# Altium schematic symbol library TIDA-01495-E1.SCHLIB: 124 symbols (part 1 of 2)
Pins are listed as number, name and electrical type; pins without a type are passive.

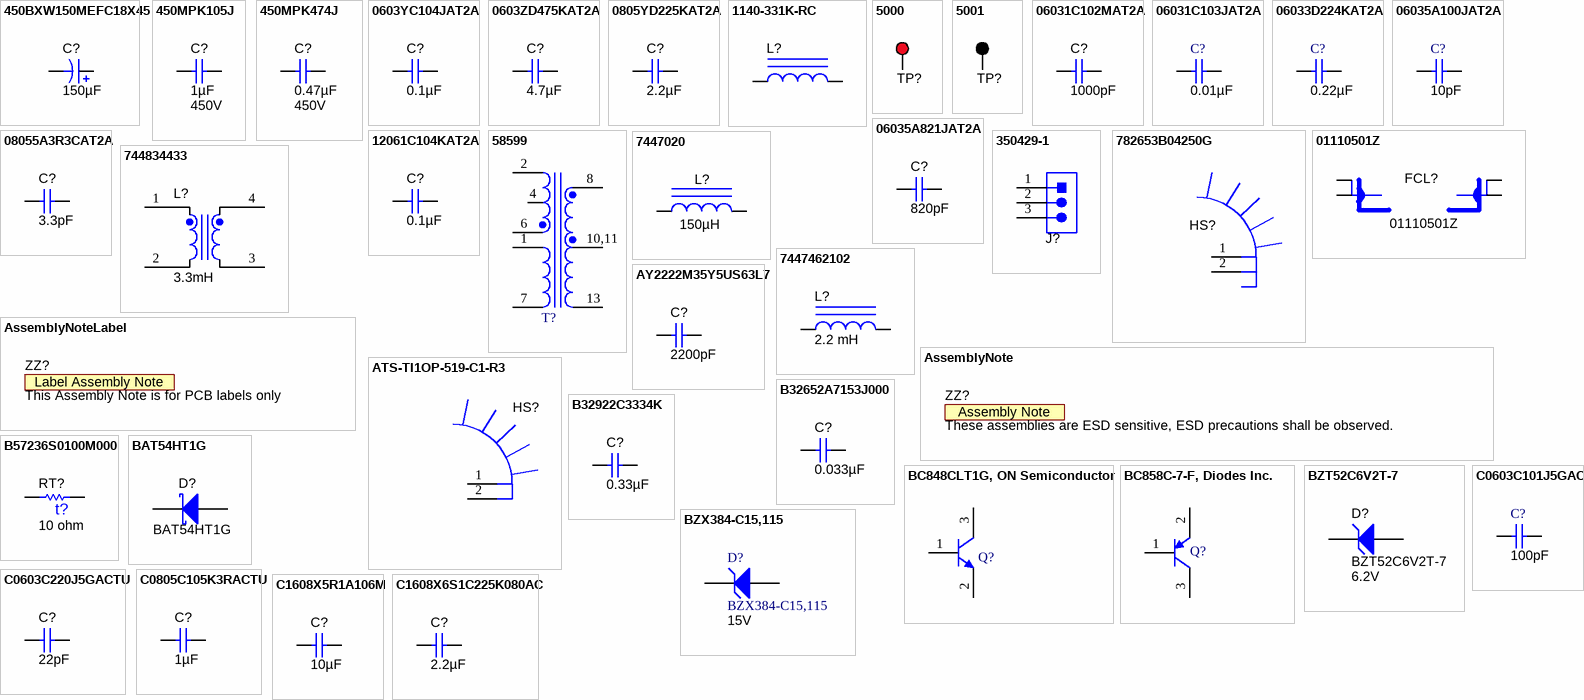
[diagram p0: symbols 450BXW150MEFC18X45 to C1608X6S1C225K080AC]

## 450BXW150MEFC18X45
designator C?  ValueDisplayed: 150µF  (hidden comment: 450BXW150MEFC18X45)
CAP, AL, 150 µF, 450 V, +/- 20%, TH; Manufacturer: Rubycon; Polarized: Y; CompType: Capacitor; Value: 150uF; U/M: EA; Cap_F: 0.00015; Tolerance_%: 20; VDC_V: 450; Value2: 450V; IRMS_A: 1; TaMin_C: -40; TaMax_C: 105; Cap_Case: 18x45mm; SizeAreaWB_mm2: 400; SizeArea_mm2: 324; SizeX_mm: 18; SizeZ_mm: 47; AEC Category: Q200; AEC Qualified: N; Green_Lifecycle: Not Set; Green_REACh: Incomplete
signal-integrity model Cap
simulation model Cap
footprint BXW_1800x4500
footprint KXG_1800x4000_horizontalDown (TH, 2-Leads, Dia 18mm, Pin Spacing 7.5mm)
pins: 1 +, 2 -

## 450MPK105J
designator C?  ValueDisplayed: 1µF  Value2: 450V  (hidden comment: 450MPK105J)
CAP, Film, 1 µF, 450 V, +/- 5%, TH; Manufacturer: Rubycon; Polarized: N; CompType: Capacitor; Value: 1uF; U/M: EA; Cap_F: 0.000001; Tolerance_%: 5; Value1: Unknown; VDC_V: 450; TaMin_C: -40; TaMax_C: 105; Cap_Case: 18x9.5mm
signal-integrity model Cap
simulation model Cap
footprint MPK_1800x950
pins: 1, 2

## 450MPK474J
designator C?  ValueDisplayed: 0.47µF  Value2: 450V  (hidden comment: 450MPK474J)
CAP, Film, 0.47 µF, 450 V, +/- 5%, TH; Manufacturer: Rubycon; Polarized: N; CompType: Capacitor; Value: 0.47uF; U/M: EA; Cap_F: 0.00000047; Tolerance_%: 5; Value1: Unknown; VDC_V: 450; TaMin_C: -40; TaMax_C: 105; Cap_Case: 18x6.5mm; AEC Category: Q200
signal-integrity model Cap
simulation model Cap
footprint MPK_1800x650
pins: 1, 2

## 0603YC104JAT2A
designator C?  ValueDisplayed: 0.1µF  (hidden comment: 0603YC104JAT2A)
CAP, CERM, 0.1 µF, 16 V, +/- 5%, X7R, 0603; Manufacturer: AVX; Polarized: N; CompType: Capacitor; Value: 0.1uF; U/M: EA; Cap_F: 0.0000001; Tolerance_%: 5; ESR_ohm: 0.039; Value1: 0.039 ohm; VDC_V: 16; Value2: 16V; TaMin_C: -55; TaMax_C: 125; Cap_Case: 0603
signal-integrity model Cap
simulation model Cap
footprint 0603
footprint 0603M
footprint 0603L
footprint 0603_HV
footprint 0603S
pins: 1, 2

## 0603ZD475KAT2A
designator C?  ValueDisplayed: 4.7µF  (hidden comment: 0603ZD475KAT2A)
CAP, CERM, 4.7 µF, 10 V, +/- 10%, X5R, 0603; Manufacturer: AVX; Polarized: N; CompType: Capacitor; Value: 4.7uF; U/M: EA; Cap_F: 0.0000047; Tolerance_%: 10; Value1: Unknown; Value2: 10V; TaMin_C: -55; TaMax_C: 85; Cap_Case: 0603; SizeArea_mm2: 1.28; SizeAreaWB_mm2: 4.68; SizeX_mm: 1.6; SizeY_mm: 0.8; SizeZ_mm: 1; AEC Category: Q200; Green_Lifecycle: Active; Green_REACh: Passed
signal-integrity model Cap
simulation model Cap
footprint 0603
footprint 0603M
footprint 0603L
footprint 0603_HV
footprint 0603S
pins: 1, 2

## 0805YD225KAT2A
designator C?  ValueDisplayed: 2.2µF  (hidden comment: 0805YD225KAT2A)
CAP, CERM, 2.2 µF, 16 V, +/- 10%, X5R, 0805; Manufacturer: AVX; Polarized: N; CompType: Capacitor; Value: 2.2uF; U/M: EA; Cap_F: 0.0000022; Tolerance_%: 10; ESR_ohm: 0.009; Value1: 0.009 ohm; VDC_V: 16; Value2: 16V; TaMin_C: -55; TaMax_C: 85; Cap_Case: 0805
signal-integrity model Cap
simulation model Cap
footprint 0805_HV
footprint 0805
footprint 0805M
footprint 0805L
pins: 1, 2

## 1140-331K-RC
designator L?
Inductor, Ferrite, 330 µH, 6.1 A, 0.074 ohm, TH; DCR_ohm: 0.074; AEC Category: Q200
signal-integrity model Inductor
simulation model Inductor
footprint IND_CUST
pins: 1, 2

## 5000
designator TP?  (value not drawn)
Test Point, Miniature, Red, TH; Manufacturer: Keystone; CompType: Test Point Loop; U/M: EA
footprint Keystone5000
pins: 1

## 5001
designator TP?  (value not drawn)
Test Point, Miniature, Black, TH; Manufacturer: Keystone; CompType: Test Point Loop; U/M: EA
footprint Keystone5001
pins: 1

## 06031C102MAT2A
designator C?  ValueDisplayed: 1000pF  (hidden comment: 06031C102MAT2A)
CAP, CERM, 1000 pF, 100 V, +/- 20%, X7R, 0603; Manufacturer: AVX; Polarized: N; CompType: Capacitor; Value: 1000pF; U/M: EA; Cap_F: 0.000000001; Tolerance_%: 20; ESR_ohm: 0.276; Value1: 0.276 ohm; VDC_V: 100; Value2: 100V; TaMin_C: -55; TaMax_C: 125; Cap_Case: 0603
signal-integrity model Cap
simulation model Cap
footprint 0603
footprint 0603M
footprint 0603L
footprint 0603_HV
footprint 0603S
pins: 1, 2

## 06031C103JAT2A
designator C?  ValueDisplayed: 0.01µF  (hidden comment: 06031C103JAT2A)
CAP, CERM, 0.01 µF, 100 V, +/- 5%, X7R, 0603; Manufacturer: AVX; Polarized: N; CompType: Capacitor; Value: 0.01uF; U/M: EA; Cap_F: 0.00000001; Tolerance_%: 5; ESR_ohm: 0.098; Value1: 0.098 ohm; VDC_V: 100; Value2: 100V; TaMin_C: -55; TaMax_C: 125; Cap_Case: 0603
signal-integrity model Cap
simulation model Cap
footprint 0603
footprint 0603M
footprint 0603L
footprint 0603_HV
footprint 0603S
pins: 1, 2

## 06033D224KAT2A
designator C?  ValueDisplayed: 0.22µF  (hidden comment: 06033D224KAT2A)
CAP, CERM, 0.22 µF, 25 V, +/- 10%, X5R, 0603; Manufacturer: AVX; Polarized: N; CompType: Capacitor; Value: 0.22uF; U/M: EA; Cap_F: 0.00000022; Tolerance_%: 10; ESR_ohm: 0.036; Value1: 0.036 ohm; VDC_V: 25; Value2: 25V; TaMin_C: -55; TaMax_C: 85; Cap_Case: 0603
signal-integrity model Cap
simulation model Cap
footprint 0603
footprint 0603M
footprint 0603L
footprint 0603_HV
footprint 0603S
pins: 1, 2

## 06035A100JAT2A
designator C?  ValueDisplayed: 10pF  (hidden comment: 06035A100JAT2A)
CAP, CERM, 10 pF, 50 V, +/- 5%, C0G/NP0, 0603; Manufacturer: AVX; Polarized: N; CompType: Capacitor; Value: 10pF; U/M: EA; Cap_F: 0.00000000001; Tolerance_%: 5; ESR_ohm: 0.403; Value1: 0.403 ohm; VDC_V: 50; Value2: 50V; TaMin_C: -55; TaMax_C: 125; Cap_Case: 0603
signal-integrity model Cap
simulation model Cap
footprint 0603
footprint 0603M
footprint 0603L
footprint 0603_HV
footprint 0603S
pins: 1, 2

## 06035A821JAT2A
designator C?  ValueDisplayed: 820pF  (hidden comment: 06035A821JAT2A)
CAP, CERM, 820 pF, 50 V, +/- 5%, C0G/NP0, 0603; Manufacturer: AVX; Polarized: N; CompType: Capacitor; Value: 820pF; U/M: EA; Cap_F: 0.00000000082; Tolerance_%: 5; ESR_ohm: 0.052; Value1: 0.052 ohm; VDC_V: 50; Value2: 50V; TaMin_C: -55; TaMax_C: 125; Cap_Case: 0603
signal-integrity model Cap
simulation model Cap
footprint 0603
footprint 0603M
footprint 0603L
footprint 0603_HV
footprint 0603S
pins: 1, 2

## 08055A3R3CAT2A
designator C?  ValueDisplayed: 3.3pF  (hidden comment: 08055A3R3CAT2A)
CAP, CERM, 3.3 pF, 50 V, +/- 8%, C0G/NP0, 0805; Manufacturer: AVX; Polarized: N; CompType: Capacitor; Value: 3.3pF; U/M: EA; Cap_F: 0.0000000000033; Tolerance_%: 8; ESR_ohm: 3.467; Value1: 3.467 ohm; VDC_V: 50; Value2: 50V; TaMin_C: -55; TaMax_C: 125; Cap_Case: 0805; SizeArea_mm2: 2.5; SizeAreaWB_mm2: 6.75; SizeX_mm: 2; SizeY_mm: 1.25; SizeZ_mm: 1.45; AEC Category: Q200; Green_Lifecycle: Not Set; Green_REACh: Incomplete
signal-integrity model Cap
simulation model Cap
footprint 0805_HV
footprint 0805_HV1
footprint 0805
footprint 0805M
footprint 0805L
pins: 1, 2

## 12061C104KAT2A
designator C?  ValueDisplayed: 0.1µF  (hidden comment: 12061C104KAT2A)
CAP, CERM, 0.1 µF, 100 V, +/- 10%, X7R, 1206; Manufacturer: AVX; Polarized: N; CompType: Capacitor; Value: 0.1uF; U/M: EA; Cap_F: 0.0000001; Tolerance_%: 10; ESR_ohm: 0.037; Value1: 0.037 ohm; VDC_V: 100; Value2: 100V; TaMin_C: -55; TaMax_C: 125; Cap_Case: 1206; SizeArea_mm2: 5.12; SizeAreaWB_mm2: 10.92; SizeX_mm: 3.2; SizeY_mm: 1.6; SizeZ_mm: 1.35; AEC Category: Q200; Green_Lifecycle: Active; Green_REACh: Passed
signal-integrity model Cap
simulation model Cap
footprint 1206
footprint 1206M
footprint 1206L
pins: 1, 2

## 58599
designator T?  (value not drawn)
Transformer, TH; Manufacturer: Payton; SymbolCreator: Altium; U/M: EA
footprint Payton_58599
footprint PCBComponent_1 - duplicate
footprint WE_750343661_CUS (TRANSFORMER, TH, 14-PIN)
pins: 1, 2, 4, 6, 7, 8, 10,11, 11, 13

## 350429-1
designator J?  (value not drawn)
Header(Shrouded), 6.35mm, 3x1, Tin, TH; Manufacturer: TE Connectivity; SymbolCreator: a0799628; U/M: EA
footprint TE_350429-1
pins: 1, 2, 3
3 alternate drawings of the same symbol

## 782653B04250G
designator HS?  (value not drawn)
HEATSINK VERT MAX CLIP, BLACK, 4.25 INCHES; Manufacturer: Aavid; SymbolCreator: a0411947
footprint HEATSINK_782653B04250G (Aavid)
pins: 1, 2

## 01110501Z
designator FCL?
FUSE CLIP, CARTRIDGE, 250V, 10A, PCB; Manufacturer: LITTELFUSE; SymbolCreator: x0199378
footprint LITTELFUSE_01110501Z (FUSE CLIP, CARTRIDGE, 250V, 10A, PCB)
pins: 1, 2, 3, 4

## 7447020
designator L?, comment ValueDisplayed: 150µH  (hidden comment: 7447076)
Inductor, Toroid, Powdered Iron, 150 µH, 5A, TH; Manufacturer: Wurth Elektronik; Value: 150uH; Value1: 0.16 ohm
signal-integrity model Inductor
simulation model Inductor
footprint IND_7447020
pins: 1, 2

## 744834433
designator L?  ValueDisplayed: 3.3mH  (hidden comment: 744834433)
Coupled inductor, 3.3 mH, 5 A, 0.037 ohm, TH; Manufacturer: Wurth Elektronik; SymbolCreator: a0412235; Value: 3.3mH; Ind_H: 3.3E-3; DCR_ohm: 0.037; AEC Category: Q200
footprint WE-CMBH
pins: 1, 2, 3, 4
1 alternate drawing of the same symbol

## 7447462102
designator L?, comment ValueDisplayed: 2.2 mH  (hidden comment: 744741222)
FIXED IND 2.2MH 210MA 11 OHM TH; Manufacturer: Wurth Elektronik; CompType: Inductor; Value: 1mH; Ind_H: 1.0E-3; Irms: 0.25A @ 40C rise; Isat: 0.27A @ 10% inductance drop; DCR_ohm: 4.38; Value1: 4.38 ohm; Value2: 0.25A; Material: Ferrite; SizeAreaWB_mm2: 64; SizeArea_mm2: 36; SizeX_mm: 6; SizeZ_mm: 8.5; AEC Category: Q200; Green_Lifecycle: Active; Green_REACh: Passed
signal-integrity model Inductor
simulation model Inductor
footprint WE-TI_5075
pins: 1, 2

## AssemblyNote
designator ZZ?, comment These assemblies are ESD sensitive, ESD precautions shall be observed.  (no BOM)
SymbolCreator: codlsc; CompType: AssemblyNote
footprint AssemblyNote

## AssemblyNoteLabel
designator ZZ?, comment This Assembly Note is for PCB labels only  (no BOM)
SymbolCreator: a0412235
footprint AssemblyNoteLabel

## ATS-TI1OP-519-C1-R3
designator HS?
Heat Sink, Vertical; Manufacturer: Advanced Thermal Solutions; SymbolCreator: a0799628; Green_Lifecycle: Not Set; Green_REACh: Incomplete
footprint HEATSINK_782653B04250G - duplicate (Aavid)
footprint HEATSINK_782653B04250G - duplicate1 (Aavid)
pins: 1, 2

## AY2222M35Y5US63L7
designator C?  ValueDisplayed: 2200pF  (hidden comment: AY2222M35Y5US63L7)
CAP, CERM, 2200 pF, 300 V, +/- 20%, Y5U, AEC-Q200 Grade 1, D9.5xT5mm; Manufacturer: Vishay-Bccomponents; Polarized: N; CompType: Capacitor; Value: 2200pF; U/M: EA; Cap_F: 0.0000000022; Tolerance_%: 20; Value1: Unknown; VDC_V: 300; Value2: 300V; TaMin_C: -55; TaMax_C: 125; Cap_Case: 9.5x5mm; SizeArea_mm2: 47.5; SizeAreaWB_mm2: 80.5; SizeX_mm: 9.5; SizeY_mm: 5; SizeZ_mm: 14.5; AEC Category: Q200; AEC Qualified: Y; AEC Grade: 1
signal-integrity model Cap
simulation model Cap
footprint CD45_700x600x1100 (TH, 2-Leads, Dia 7mm, Pin Spacing 10 mm)
pins: 1, 2

## B32652A7153J000
designator C?, comment ValueDisplayed: 0.033µF  (hidden comment: B32642B0333J)
CAP FILM 0.033UF 5% 1KVDC RADIAL; Manufacturer: TDK; Polarized: N; CompType: Capacitor; U/M: EA; Cap_F: 0.000000033; Tolerance_%: 5; VDC_V: 1250; Value2: 1250V; TaMin_C: -55; TaMax_C: 100; Cap_Case: 18x7x12.5; SizeAreaWB_mm2: 180; SizeArea_mm2: 126; SizeX_mm: 18; SizeY_mm: 7; SizeZ_mm: 12.5; AEC Category: Q200; AEC Qualified: Y; AEC Grade: 3; Green_Lifecycle: Not Set; Green_REACh: Incomplete; VAC: 500
signal-integrity model Cap
simulation model Cap
footprint B32652_1800x700x1250
pins: 1, 2

## B32922C3334K
designator C?  ValueDisplayed: 0.33µF  (hidden comment: B32922C3334K)
CAP, Film, 0.33 µF, X2 305 VAC, +/- 10%, TH; Manufacturer: TDK; Polarized: N; CompType: Capacitor; Value: 0.33uF; U/M: EA; Cap_F: 0.00000033; Tolerance_%: 10; TaMin_C: -40; TaMax_C: 110; Cap_Case: 18x8x14.5mm; SizeAreaWB_mm2: 210; SizeArea_mm2: 153; SizeX_mm: 18; SizeY_mm: 8.5; SizeZ_mm: 14.5; AEC Category: Q200; VAC_X: 305
signal-integrity model Cap
simulation model Cap
footprint B32922_14.5mm
pins: 1, 2

## B57236S0100M000
designator RT?  value 10 ohm  (hidden comment: B57236S0100M000)
Thermistor NTC, 10 ohm, 20%, Disc_11.5mmx6mm; Manufacturer: EPCOS Inc; Tolerance_%: 20; Power_W: 2.1; TaMin_C: -55; TaMax_C: 170; U/M: EA
footprint THERM_B57236S0
pins: 1, 2

## BAT54HT1G
designator D?
Diode, Schottky, 30V, 0.2A, SOD-323; Manufacturer: ON Semiconductor; Value: 0.35V; U/M: EA; Vf_V: 0.35; Io_A: 0.2; Vr_V: 30
signal-integrity model Diode
footprint sod-323
pins: 1 K, 2 A

## BC848CLT1G, ON Semiconductor
designator Q?, comment BC848CLT1G  (value not drawn)
Transistor, NPN, 30 V, 0.1 A, SOT-23; Manufacturer: ON Semiconductor; CompType: BJT; PNP: 0; NPN: 1; Vceo_V: 30; Vcesat1_V: 0.7; Value: 30 V; IcRated_A: 0.1; Value1: 0.1 A; HfeMax: 800; TaMin_C: -55; TaMax_C: 150; U/M: EA
footprint SOT-23
footprint SOT-23M
footprint SOT-23L
pins: 1 B, 2 E, 3 C

## BC858C-7-F, Diodes Inc.
designator Q?, comment BC858C-7-F  (value not drawn)
Transistor, PNP, 30 V, 0.1 A, SOT-23; Manufacturer: Diodes Inc.; CompType: BJT; PNP: 1; NPN: 0; Vceo_V: 30; Vcesat1_V: 0.075; Value: 30 V; IcRated_A: 0.1; Value1: 0.1 A; HfeMax: 600; TaMin_C: -65; TaMax_C: 150; U/M: EA
footprint SOT-23
footprint SOT-23M
footprint SOT-23L
simulation model DI_BC858C
pins: 1 B, 2 E, 3 C

## BZT52C6V2T-7
designator D?  value 6.2V
Diode, Zener, 6.2 V, 300 mW, SOD-523; Manufacturer: Diodes Inc.; SymbolCreator: a0412235; U/M: EA; Power_W: 0.3; Vz_V: 6.2; Value1: 0.3W; RJA_CperW: 417; SizeAreaWB_mm2: 5.13; SizeArea_mm2: 1.53; SizeX_mm: 1.7; SizeY_mm: 0.9; SizeZ_mm: 0.65; AEC Category: Q101
signal-integrity model Diode
footprint SOD-523
pins: 1 K, 2 A

## BZX384-C15,115
designator D?  value 15V
Diode, Zener, 15 V, 300 mW, SOD-323; Manufacturer: NXP Semiconductor; SymbolCreator: a0412235; U/M: EA; Power_W: 0.3; Vz_V: 15; Value1: 0.3W; RJA_CperW: 415
signal-integrity model Diode
footprint sod-323
pins: 1 K, 2 A

## C0603C101J5GAC
designator C?  ValueDisplayed: 100pF  (hidden comment: C0603C101J5GAC)
CAP, CERM, 100 pF, 50 V, +/- 5%, C0G/NP0, 0603; Manufacturer: Kemet; Polarized: N; CompType: Capacitor; Value: 100pF; U/M: EA; Cap_F: 0.0000000001; Tolerance_%: 5; Value1: Unknown; VDC_V: 50; Value2: 50V; TaMin_C: -55; TaMax_C: 125; Cap_Case: 0603
signal-integrity model Cap
simulation model Cap
footprint 0603
footprint 0603M
footprint 0603L
footprint 0603_HV
footprint 0603S
pins: 1, 2

## C0603C220J5GACTU
designator C?  ValueDisplayed: 22pF  (hidden comment: C0603C220J5GACTU)
CAP, CERM, 22 pF, 50 V, +/- 5%, C0G/NP0, 0603; Manufacturer: Kemet; Polarized: N; CompType: Capacitor; Value: 22pF; U/M: EA; Cap_F: 0.000000000022; Tolerance_%: 5; Value1: Unknown; VDC_V: 50; Value2: 50V; TaMin_C: -55; TaMax_C: 125; Cap_Case: 0603
signal-integrity model Cap
simulation model Cap
footprint 0603
footprint 0603M
footprint 0603L
footprint 0603_HV
footprint 0603S
pins: 1, 2

## C0805C105K3RACTU
designator C?  ValueDisplayed: 1µF  (hidden comment: C0805C105K3RACTU)
CAP, CERM, 1 µF, 25 V, +/- 10%, X7R, 0805; Manufacturer: Kemet; Polarized: N; CompType: Capacitor; Value: 1uF; U/M: EA; Cap_F: 0.000001; Tolerance_%: 10; Value1: Unknown; VDC_V: 25; Value2: 25V; TaMin_C: -55; TaMax_C: 125; Cap_Case: 0805; SizeArea_mm2: 2.5; SizeAreaWB_mm2: 6.75; SizeX_mm: 2; SizeY_mm: 1.25; SizeZ_mm: 1.45; AEC Category: Q200; Green_Lifecycle: Active; Green_REACh: Passed
signal-integrity model Cap
simulation model Cap
footprint 0805_HV
footprint 0805_HV1
footprint 0805
footprint 0805M
footprint 0805L
pins: 1, 2

## C1608X5R1A106M
designator C?  ValueDisplayed: 10µF  (hidden comment: C1608X5R1A106M)
CAP, CERM, 10 µF, 10 V, +/- 20%, X5R, 0603; Manufacturer: TDK; Polarized: N; CompType: Capacitor; Value: 10uF; U/M: EA; Cap_F: 0.00001; Tolerance_%: 20; ESR_ohm: 0.0078; Value1: 0.0078 ohm; VDC_V: 10; Value2: 10V; IRMS_A: 1.85; TaMin_C: -55; TaMax_C: 85; Cap_Case: 0603
signal-integrity model Cap
simulation model Cap
footprint 0603 (0603 from SM-752 data)
footprint 0603M
footprint 0603L
footprint 0603_HV
footprint 0603S
pins: 1, 2

## C1608X6S1C225K080AC
designator C?  ValueDisplayed: 2.2µF  (hidden comment: C1608X6S1C225K080AC)
CAP, CERM, 2.2 µF, 16 V, +/- 10%, X6S, 0603; Manufacturer: TDK; Polarized: N; CompType: Capacitor; Value: 2.2uF; U/M: EA; Cap_F: 0.0000022; Tolerance_%: 10; ESR_ohm: 0.007674; Value1: 0.007674 ohm; VDC_V: 16; Value2: 16V; IRMS_A: 1.87823; TaMin_C: -55; TaMax_C: 105; Cap_Case: 0603; SizeArea_mm2: 1.28; SizeAreaWB_mm2: 4.68; SizeX_mm: 1.6; SizeY_mm: 0.8; SizeZ_mm: 1; AEC Category: Q200
signal-integrity model Cap
simulation model Cap
footprint 0603
footprint 0603M
footprint 0603L
footprint 0603_HV
footprint 0603S
pins: 1, 2

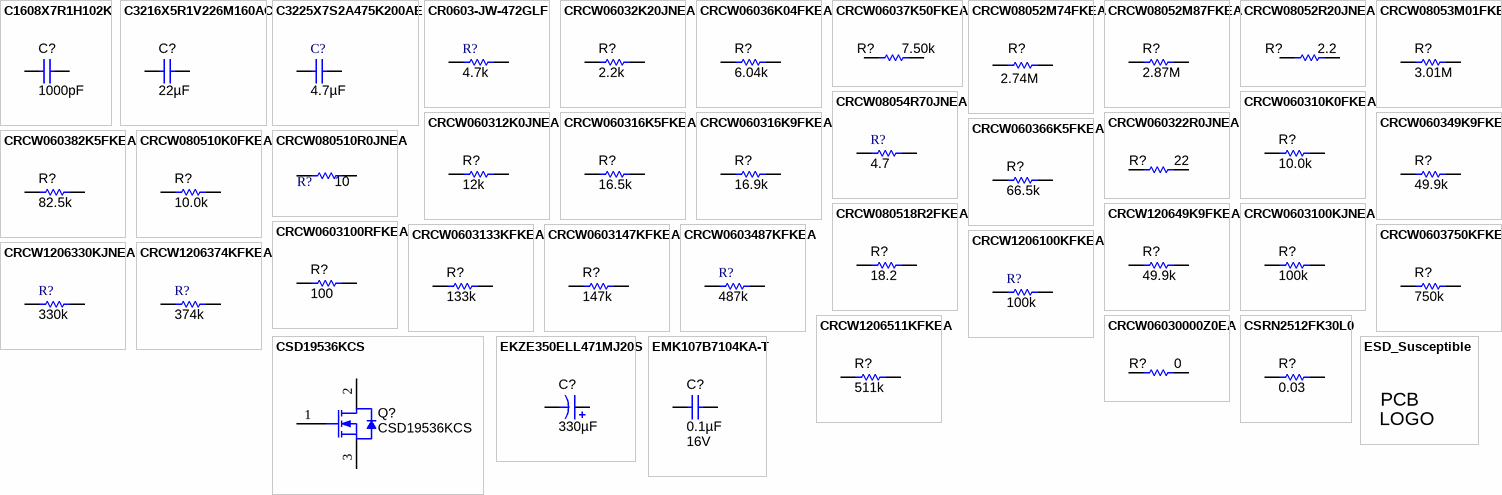
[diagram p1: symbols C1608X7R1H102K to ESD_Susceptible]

## C1608X7R1H102K
designator C?  ValueDisplayed: 1000pF  (hidden comment: C1608X7R1H102K)
CAP, CERM, 1000 pF, 50 V, +/- 10%, X7R, 0603; Manufacturer: TDK; Polarized: N; CompType: Capacitor; Value: 1000pF; U/M: EA; Cap_F: 0.000000001; Tolerance_%: 10; ESR_ohm: 0.24; Value1: 0.24 ohm; VDC_V: 50; Value2: 50V; TaMin_C: -55; TaMax_C: 125; Cap_Case: 0603
signal-integrity model Cap
simulation model Cap
footprint 0603 (0603 from SM-752 data)
footprint 0603M
footprint 0603L
footprint 0603_HV
footprint 0603S
pins: 1, 2

## C3216X5R1V226M160AC
designator C?  ValueDisplayed: 22µF  (hidden comment: C3216X5R1V226M160AC)
CAP, CERM, 22 µF, 35 V,+/- 20%, X5R, 1206; Manufacturer: TDK; Polarized: N; CompType: Capacitor; Value: 22uF; U/M: EA; Cap_F: 0.000022; Tolerance_%: 20; ESR_ohm: 0.002398; Value1: 0.002398 ohm; VDC_V: 35; Value2: 35V; IRMS_A: 4.68507; TaMin_C: -55; TaMax_C: 85; Cap_Case: 1206; SizeArea_mm2: 5.12; SizeAreaWB_mm2: 10.92; SizeX_mm: 3.2; SizeY_mm: 1.6; SizeZ_mm: 1.8; AEC Category: Q200; Green_Lifecycle: Active; Green_REACh: Passed
signal-integrity model Cap
simulation model Cap
footprint 1206_180
footprint 1206_180M
footprint 1206_180L
pins: 1, 2

## C3225X7S2A475K200AE
designator C?  ValueDisplayed: 4.7µF  (hidden comment: C3225X7S2A475K200AE)
CAP, CERM, 4.7 µF, 100 V, +/- 10%, X7S, 1210; Manufacturer: TDK; Polarized: N; CompType: Capacitor; Value: 4.7uF; U/M: EA; Cap_F: 0.0000047; Tolerance_%: 10; Value1: Unknown; VDC_V: 100; Value2: 100V; TaMin_C: -55; TaMax_C: 125; Cap_Case: 1210
signal-integrity model Cap
simulation model Cap
footprint 1210
footprint 1210M
footprint 1210L
pins: 1, 2

## CR0603-JW-472GLF
designator R?  ValueDisplayed: 4.7k  (hidden comment: CR0603-JW-472GLF)
RES, 4.7 k, 5%, 0.1 W, 0603; Manufacturer: Bourns; CompType: Resistor; Value: 4.7k; Res_ohm: 4700; Value_Code: 4k70; Tolerance_%: 5; Power_W: 0.1; Value2: 0.1W; VDC_V: 50; TempCo: 200 ppm/C; EIA_Code: E24; U/M: EA
signal-integrity model Resistor
simulation model Resistor
footprint 0603
footprint 0603M
footprint 0603L
footprint 0603_HV
footprint 0603S
pins: 1, 2

## CRCW06032K20JNEA
designator R?  ValueDisplayed: 2.2k  (hidden comment: CRCW06032K20JNEA)
RES, 2.2 k, 5%, 0.1 W, 0603; Manufacturer: Vishay-Dale; CompType: Resistor; Value: 2.2k; Res_ohm: 2200; Value_Code: 2k20; Tolerance_%: 5; Power_W: 0.1; Value2: 0.1W; VDC_V: 75; TempCo: 200 ppm/C; EIA_Code: E24; U/M: EA
signal-integrity model Resistor
simulation model Resistor
footprint 0603
footprint 0603M
footprint 0603L
footprint 0603_HV
footprint 0603S
pins: 1, 2

## CRCW06036K04FKEA
designator R?  ValueDisplayed: 6.04k  (hidden comment: CRCW06036K04FKEA)
RES, 6.04 k, 1%, 0.1 W, 0603; Manufacturer: Vishay-Dale; CompType: Resistor; Value: 6.04k; Res_ohm: 6040; Value_Code: 6k04; Tolerance_%: 1; Power_W: 0.1; Value2: 0.1W; VDC_V: 75; TempCo: 100 ppm/C; SizeArea_mm2: 1.28; SizeX_mm: 1.6; SizeY_mm: 0.8; EIA_Code: E96; U/M: EA; AEC Category: Q200; Green_Lifecycle: Active; Green_REACh: Passed
signal-integrity model Resistor
simulation model Resistor
footprint 0603
footprint 0603M
footprint 0603L
footprint 0603_HV
footprint 0603S
pins: 1, 2

## CRCW06037K50FKEA
designator R?  ValueDisplayed: 7.50k  (hidden comment: CRCW06037K50FKEA)
RES, 7.50 k, 1%, 0.1 W, 0603; Manufacturer: Vishay-Dale; CompType: Resistor; Value: 7.50k; Res_ohm: 7500; Value_Code: 7k50; Tolerance_%: 1; Power_W: 0.1; Value2: 0.1W; VDC_V: 75; TempCo: 100 ppm/C; EIA_Code: E96; U/M: EA
signal-integrity model Resistor
simulation model Resistor
footprint 0603
footprint 0603M
footprint 0603L
footprint 0603_HV
footprint 0603S
pins: 1, 2

## CRCW08052M74FKEA
designator R?  ValueDisplayed: 2.74M  (hidden comment: CRCW08052M74FKEA)
RES, 2.74 M, 1%, 0.125 W, 0805; Manufacturer: Vishay-Dale; CompType: Resistor; Value: 2.74Meg; Res_ohm: 2740000; Value_Code: 2M74; Tolerance_%: 1; Power_W: 0.125; Value2: 0.125W; VDC_V: 150; TempCo: 100 ppm/C; EIA_Code: E96; U/M: EA
signal-integrity model Resistor
simulation model Resistor
footprint 0805_HV
footprint 0805
footprint 0805M
footprint 0805L
pins: 1, 2

## CRCW08052M87FKEA
designator R?  ValueDisplayed: 2.87M  (hidden comment: CRCW08052M87FKEA)
RES, 2.87 M, 1%, 0.125 W, 0805; Manufacturer: Vishay-Dale; CompType: Resistor; Value: 2.87Meg; Res_ohm: 2870000; Value_Code: 2M87; Tolerance_%: 1; Power_W: 0.125; Value2: 0.125W; VDC_V: 150; TempCo: 100 ppm/C; EIA_Code: E96; U/M: EA
signal-integrity model Resistor
simulation model Resistor
footprint 0805_HV
footprint 0805
footprint 0805M
footprint 0805L
pins: 1, 2

## CRCW08052R20JNEA
designator R?  ValueDisplayed: 2.2  (hidden comment: CRCW08052R20JNEA)
RES, 2.2, 5%, 0.125 W, 0805; Manufacturer: Vishay-Dale; CompType: Resistor; Value: 2.2; Value_Code: 2R20; Tolerance_%: 5; Power_W: 0.125; Value2: 0.125W; VDC_V: 150; TempCo: 200 ppm/C; SizeArea_mm2: 2.5; SizeX_mm: 2; SizeY_mm: 1.25; SizeZ_mm: 1.45; EIA_Code: E24; U/M: EA; AEC Category: Q200; Green_Lifecycle: Active; Green_REACh: Passed
signal-integrity model Resistor
simulation model Resistor
footprint 0805_HV
footprint 0805_HV1
footprint 0805
footprint 0805M
footprint 0805L
pins: 1, 2

## CRCW08053M01FKEA
designator R?  ValueDisplayed: 3.01M  (hidden comment: CRCW08053M01FKEA)
RES, 3.01 M, 1%, 0.125 W, 0805; Manufacturer: Vishay-Dale; CompType: Resistor; Value: 3.01Meg; Res_ohm: 3010000; Value_Code: 3M01; Tolerance_%: 1; Power_W: 0.125; Value2: 0.125W; VDC_V: 150; TempCo: 100 ppm/C; EIA_Code: E96; U/M: EA
signal-integrity model Resistor
simulation model Resistor
footprint 0805_HV
footprint 0805
footprint 0805M
footprint 0805L
pins: 1, 2

## CRCW08054R70JNEA
designator R?  ValueDisplayed: 4.7  (hidden comment: CRCW08054R70JNEA)
RES, 4.7, 5%, 0.125 W, 0805; Manufacturer: Vishay-Dale; CompType: Resistor; Value: 4.7; Value_Code: 4R70; Tolerance_%: 5; Power_W: 0.125; Value2: 0.125W; VDC_V: 150; TempCo: 200 ppm/C; EIA_Code: E24; U/M: EA
signal-integrity model Resistor
simulation model Resistor
footprint 0805_HV
footprint 0805_HV1
footprint 0805
footprint 0805M
pins: 1, 2

## CRCW060310K0FKEA
designator R?  ValueDisplayed: 10.0k  (hidden comment: CRCW060310K0FKEA)
RES, 10.0 k, 1%, 0.1 W, 0603; Manufacturer: Vishay-Dale; CompType: Resistor; Value: 10.0k; Res_ohm: 10000; Value_Code: 10k0; Tolerance_%: 1; Power_W: 0.1; Value2: 0.1W; VDC_V: 75; TempCo: 100 ppm/C; SizeArea_mm2: 1.28; SizeX_mm: 1.6; SizeY_mm: 0.8; EIA_Code: E96; U/M: EA; AEC Category: Q200; Green_Lifecycle: Active; Green_REACh: Passed
signal-integrity model Resistor
simulation model Resistor
footprint 0603
footprint 0603M
footprint 0603L
footprint 0603_HV
footprint 0603S
pins: 1, 2

## CRCW060312K0JNEA
designator R?  ValueDisplayed: 12k  (hidden comment: CRCW060312K0JNEA)
RES, 12 k, 5%, 0.1 W, 0603; Manufacturer: Vishay-Dale; CompType: Resistor; Value: 12k; Res_ohm: 12000; Value_Code: 12k0; Tolerance_%: 5; Power_W: 0.1; Value2: 0.1W; VDC_V: 75; TempCo: 200 ppm/C; EIA_Code: E24; U/M: EA
signal-integrity model Resistor
simulation model Resistor
footprint 0603
footprint 0603M
footprint 0603L
footprint 0603_HV
footprint 0603S
pins: 1, 2

## CRCW060316K5FKEA
designator R?  ValueDisplayed: 16.5k  (hidden comment: CRCW060316K5FKEA)
RES, 16.5 k, 1%, 0.1 W, 0603; Manufacturer: Vishay-Dale; CompType: Resistor; Value: 16.5k; Res_ohm: 16500; Value_Code: 16k5; Tolerance_%: 1; Power_W: 0.1; Value2: 0.1W; VDC_V: 75; TempCo: 100 ppm/C; EIA_Code: E96; U/M: EA
signal-integrity model Resistor
simulation model Resistor
footprint 0603
footprint 0603M
footprint 0603L
footprint 0603_HV
footprint 0603S
pins: 1, 2

## CRCW060316K9FKEA
designator R?  ValueDisplayed: 16.9k  (hidden comment: CRCW060316K9FKEA)
RES, 16.9 k, 1%, 0.1 W, 0603; Manufacturer: Vishay-Dale; CompType: Resistor; Value: 16.9k; Res_ohm: 16900; Value_Code: 16k9; Tolerance_%: 1; Power_W: 0.1; Value2: 0.1W; VDC_V: 75; TempCo: 100 ppm/C; SizeArea_mm2: 1.28; SizeX_mm: 1.6; SizeY_mm: 0.8; EIA_Code: E96; U/M: EA; AEC Category: Q200; Green_Lifecycle: Active; Green_REACh: Passed
signal-integrity model Resistor
simulation model Resistor
footprint 0603
footprint 0603M
footprint 0603L
footprint 0603_HV
footprint 0603S
pins: 1, 2

## CRCW060322R0JNEA
designator R?  ValueDisplayed: 22  (hidden comment: CRCW060322R0JNEA)
RES, 22, 5%, 0.1 W, 0603; Manufacturer: Vishay-Dale; CompType: Resistor; Value: 22; Value_Code: 22R0; Tolerance_%: 5; Power_W: 0.1; Value2: 0.1W; VDC_V: 75; TempCo: 200 ppm/C; SizeArea_mm2: 1.28; SizeX_mm: 1.6; SizeY_mm: 0.8; SizeZ_mm: 1; EIA_Code: E24; U/M: EA; AEC Category: Q200
signal-integrity model Resistor
simulation model Resistor
footprint 0603
footprint 0603M
footprint 0603L
footprint 0603_HV
footprint 0603S
pins: 1, 2

## CRCW060349K9FKEA
designator R?  ValueDisplayed: 49.9k  (hidden comment: CRCW060349K9FKEA)
RES, 49.9 k, 1%, 0.1 W, 0603; Manufacturer: Vishay-Dale; CompType: Resistor; Value: 49.9k; Res_ohm: 49900; Value_Code: 49k9; Tolerance_%: 1; Power_W: 0.1; Value2: 0.1W; VDC_V: 75; TempCo: 100 ppm/C; EIA_Code: E96; U/M: EA
signal-integrity model Resistor
simulation model Resistor
footprint 0603
footprint 0603M
footprint 0603L
footprint 0603_HV
footprint 0603S
pins: 1, 2

## CRCW060366K5FKEA
designator R?  ValueDisplayed: 66.5k  (hidden comment: CRCW060366K5FKEA)
RES, 66.5 k, 1%, 0.1 W, 0603; Manufacturer: Vishay-Dale; CompType: Resistor; Value: 66.5k; Res_ohm: 66500; Value_Code: 66k5; Tolerance_%: 1; Power_W: 0.1; Value2: 0.1W; VDC_V: 75; TempCo: 100 ppm/C; EIA_Code: E96; U/M: EA
signal-integrity model Resistor
simulation model Resistor
footprint 0603
footprint 0603M
footprint 0603L
footprint 0603_HV
footprint 0603S
pins: 1, 2

## CRCW060382K5FKEA
designator R?  ValueDisplayed: 82.5k  (hidden comment: CRCW060382K5FKEA)
RES, 82.5 k, 1%, 0.1 W, 0603; Manufacturer: Vishay-Dale; CompType: Resistor; Value: 82.5k; Res_ohm: 82500; Value_Code: 82k5; Tolerance_%: 1; Power_W: 0.1; Value2: 0.1W; VDC_V: 75; TempCo: 100 ppm/C; EIA_Code: E96; U/M: EA
signal-integrity model Resistor
simulation model Resistor
footprint 0603
footprint 0603M
footprint 0603L
footprint 0603_HV
footprint 0603S
pins: 1, 2

## CRCW080510K0FKEA
designator R?  ValueDisplayed: 10.0k  (hidden comment: CRCW080510K0FKEA)
RES, 10.0 k, 1%, 0.125 W, 0805; Manufacturer: Vishay-Dale; CompType: Resistor; Value: 10.0k; Res_ohm: 10000; Value_Code: 10k0; Tolerance_%: 1; Power_W: 0.125; Value2: 0.125W; VDC_V: 150; TempCo: 100 ppm/C; EIA_Code: E96; U/M: EA
signal-integrity model Resistor
simulation model Resistor
footprint 0805_HV
footprint 0805
footprint 0805M
footprint 0805L
pins: 1, 2

## CRCW080510R0JNEA
designator R?  ValueDisplayed: 10  (hidden comment: CRCW080510R0JNEA)
RES, 10, 5%, 0.125 W, 0805; Manufacturer: Vishay-Dale; CompType: Resistor; Value: 10; Value_Code: 10R0; Tolerance_%: 5; Power_W: 0.125; Value2: 0.125W; VDC_V: 150; TempCo: 200 ppm/C; EIA_Code: E24; U/M: EA
signal-integrity model Resistor
simulation model Resistor
footprint 0805_HV
footprint 0805_HV1
footprint 0805
footprint 0805M
pins: 1, 2

## CRCW080518R2FKEA
designator R?  ValueDisplayed: 18.2  (hidden comment: CRCW080518R2FKEA)
RES, 18.2, 1%, 0.125 W, 0805; Manufacturer: Vishay-Dale; CompType: Resistor; Value: 18.2; Value_Code: 18R2; Tolerance_%: 1; Power_W: 0.125; Value2: 0.125W; VDC_V: 150; TempCo: 100 ppm/C; SizeArea_mm2: 2.5; SizeX_mm: 2; SizeY_mm: 1.25; SizeZ_mm: 1.45; EIA_Code: E96; U/M: EA; AEC Category: Q200
signal-integrity model Resistor
simulation model Resistor
footprint 0805_HV
footprint 0805_HV1
footprint 0805
footprint 0805M
footprint 0805L
pins: 1, 2

## CRCW120649K9FKEA
designator R?  value 49.9k  (hidden comment: CRCW120649K9FKEA)
RES, 49.9k ohm, 1%, 0.25W, 1206; Manufacturer: Vishay-Dale; CompType: Resistor; Res_ohm: 49900; Value_Code: 49k9; Tolerance_%: 1; Power_W: 0.25; VDC_V: 200; TempCo: 100 ppm/C; EIA_Code: E96; U/M: EA
signal-integrity model Resistor
simulation model Resistor
footprint 1206
footprint 1206M
footprint 1206L
pins: 1, 2

## CRCW0603100KJNEA
designator R?  ValueDisplayed: 100k  (hidden comment: CRCW0603100KJNEA)
RES, 100 k, 5%, 0.1 W, 0603; Manufacturer: Vishay-Dale; CompType: Resistor; Value: 100k; Res_ohm: 100000; Tolerance_%: 5; Power_W: 0.1; Value2: 0.1W; VDC_V: 75; TempCo: 200 ppm/C; EIA_Code: E24; U/M: EA
signal-integrity model Resistor
simulation model Resistor
footprint 0603
footprint 0603M
footprint 0603L
footprint 0603_HV
footprint 0603S
pins: 1, 2

## CRCW0603100RFKEA
designator R?  ValueDisplayed: 100  (hidden comment: CRCW0603100RFKEA)
RES, 100, 1%, 0.1 W, 0603; Manufacturer: Vishay-Dale; CompType: Resistor; Value: 100; Value_Code: 100R; Tolerance_%: 1; Power_W: 0.1; Value2: 0.1W; VDC_V: 75; TempCo: 100 ppm/C; EIA_Code: E96; U/M: EA
signal-integrity model Resistor
simulation model Resistor
footprint 0603
footprint 0603M
footprint 0603L
footprint 0603_HV
footprint 0603S
pins: 1, 2

## CRCW0603133KFKEA
designator R?  ValueDisplayed: 133k  (hidden comment: CRCW0603133KFKEA)
RES, 133 k, 1%, 0.1 W, 0603; Manufacturer: Vishay-Dale; CompType: Resistor; Value: 133k; Res_ohm: 133000; Tolerance_%: 1; Power_W: 0.1; Value2: 0.1W; VDC_V: 75; TempCo: 100 ppm/C; EIA_Code: E96; U/M: EA
signal-integrity model Resistor
simulation model Resistor
footprint 0603
footprint 0603M
footprint 0603L
footprint 0603_HV
footprint 0603S
pins: 1, 2

## CRCW0603147KFKEA
designator R?  ValueDisplayed: 147k  (hidden comment: CRCW0603147KFKEA)
RES, 147 k, 1%, 0.1 W, 0603; Manufacturer: Vishay-Dale; CompType: Resistor; Value: 147k; Res_ohm: 147000; Tolerance_%: 1; Power_W: 0.1; Value2: 0.1W; VDC_V: 75; TempCo: 100 ppm/C; SizeArea_mm2: 1.28; SizeX_mm: 1.6; SizeY_mm: 0.8; EIA_Code: E96; U/M: EA; AEC Category: Q200; Green_Lifecycle: Active; Green_REACh: Passed
signal-integrity model Resistor
simulation model Resistor
footprint 0603
footprint 0603M
footprint 0603L
footprint 0603_HV
footprint 0603S
pins: 1, 2

## CRCW0603487KFKEA
designator R?  ValueDisplayed: 487k  (hidden comment: CRCW0603487KFKEA)
RES, 487 k, 1%, 0.1 W, 0603; Manufacturer: Vishay-Dale; CompType: Resistor; Value: 487k; Res_ohm: 487000; Tolerance_%: 1; Power_W: 0.1; Value2: 0.1W; VDC_V: 75; TempCo: 100 ppm/C; EIA_Code: E96; U/M: EA
signal-integrity model Resistor
simulation model Resistor
footprint 0603
footprint 0603M
footprint 0603L
footprint 0603_HV
footprint 0603S
pins: 1, 2

## CRCW0603750KFKEA
designator R?  ValueDisplayed: 750k  (hidden comment: CRCW0603750KFKEA)
RES, 750 k, 1%, 0.1 W, 0603; Manufacturer: Vishay-Dale; CompType: Resistor; Value: 750k; Res_ohm: 750000; Tolerance_%: 1; Power_W: 0.1; Value2: 0.1W; VDC_V: 75; TempCo: 100 ppm/C; SizeArea_mm2: 1.28; SizeX_mm: 1.6; SizeY_mm: 0.8; EIA_Code: E96; U/M: EA; AEC Category: Q200; Green_Lifecycle: Active; Green_REACh: Passed
signal-integrity model Resistor
simulation model Resistor
footprint 0603
footprint 0603M
footprint 0603L
footprint 0603_HV
footprint 0603S
pins: 1, 2

## CRCW1206100KFKEA
designator R?  ValueDisplayed: 100k  (hidden comment: CRCW1206100KFKEA)
RES, 100 k, 1%, 0.25 W, 1206; Manufacturer: Vishay-Dale; CompType: Resistor; Value: 100k; Res_ohm: 100000; Tolerance_%: 1; Power_W: 0.25; Value2: 0.25W; VDC_V: 200; TempCo: 100 ppm/C; EIA_Code: E96; U/M: EA
signal-integrity model Resistor
simulation model Resistor
footprint 1206
footprint 1206M
footprint 1206L
pins: 1, 2

## CRCW1206330KJNEA
designator R?  ValueDisplayed: 330k  (hidden comment: CRCW1206330KJNEA)
RES, 330 k, 5%, 0.25 W, 1206; Manufacturer: Vishay-Dale; CompType: Resistor; Value: 330k; Res_ohm: 330000; Tolerance_%: 5; Power_W: 0.25; Value2: 0.25W; VDC_V: 200; TempCo: 200 ppm/C; EIA_Code: E24; U/M: EA
signal-integrity model Resistor
simulation model Resistor
footprint 1206
footprint 1206M
footprint 1206L
pins: 1, 2

## CRCW1206374KFKEA
designator R?  ValueDisplayed: 374k  (hidden comment: CRCW1206374KFKEA)
RES, 374 k, 1%, 0.25 W, 1206; Manufacturer: Vishay-Dale; CompType: Resistor; Value: 374k; Res_ohm: 374000; Tolerance_%: 1; Power_W: 0.25; Value2: 0.25W; VDC_V: 200; TempCo: 100 ppm/C; EIA_Code: E96; U/M: EA
signal-integrity model Resistor
simulation model Resistor
footprint 1206
footprint 1206M
footprint 1206L
pins: 1, 2

## CRCW1206511KFKEA
designator R?  value 511k  (hidden comment: CRCW1206511KFKEA)
RES, 511k ohm, 1%, 0.25W, 1206; Manufacturer: Vishay-Dale; CompType: Resistor; Res_ohm: 511000; Tolerance_%: 1; Power_W: 0.25; VDC_V: 200; TempCo: 100 ppm/C; EIA_Code: E96; U/M: EA
signal-integrity model Resistor
simulation model Resistor
footprint 1206
footprint 1206M
footprint 1206L
pins: 1, 2

## CRCW06030000Z0EA
designator R?  ValueDisplayed: 0  (hidden comment: CRCW06030000Z0EA)
RES, 0, 5%, 0.1 W, 0603; Manufacturer: Vishay-Dale; CompType: Resistor; Value: 0; Value_Code: 0000; Tolerance_%: 5; Power_W: 0.1; Value2: 0.1W; VDC_V: 75; TempCo: 200 ppm/C; EIA_Code: E24; U/M: EA
signal-integrity model Resistor
simulation model Resistor
footprint 0603
footprint 0603M
footprint 0603L
footprint 0603_HV
footprint 0603S
pins: 1, 2

## CSD19536KCS
designator Q?
MOSFET, N-CH, 100 V, 150 A, KCS0003B (TO-220-3); Manufacturer: Texas Instruments; Alternate Manufacturer: None; U/M: EA; ChType: N; Value: 100V; VdsMax_V: 100; Value1: ? ohm; Value2: 118 nC; QgTyp_nC: 118; Vgs_V: 20; IdsMax_A: 150; SizeAreaWB_mm2: 79.648; SizeArea_mm2: 46.228; SizeX_mm: 4.55; SizeY_mm: 10.16; SizeZ_mm: 20.45; AEC Category: Q101
footprint TO-220AB_HORIZONTAL (For SolarMagic, with tab facing heatsink, away from PCB)
pins: 1 G, 2 D, 3 S
1 alternate drawing of the same symbol

## CSRN2512FK30L0
designator R?  ValueDisplayed: 0.03  (hidden comment: CSRN2512FK30L0)
RES, 0.03, 1%, 2 W, 2512; Manufacturer: Stackpole Electronics Inc; CompType: Resistor; Value: 0.03; Value_Code: R030; Tolerance_%: 1; Power_W: 2; Value2: 2W; TempCo: 200 ppm/C; SizeArea_mm2: 20.16; SizeX_mm: 6.3; SizeY_mm: 3.2; SizeZ_mm: 0.71; EIA_Code: E96; U/M: EA; AEC Category: Q200
signal-integrity model Resistor
simulation model Resistor
footprint 2512
footprint 2512M
footprint 2512L
pins: 1, 2

## EKZE350ELL471MJ20S
designator C?, comment ValueDisplayed: 330µF  (hidden comment: 35ZLH330MEFC10X12.5)
CAP, AL, 330 µF, 35 V, +/- 20%, TH; Manufacturer: Rubycon; Polarized: Y; CompType: Capacitor; Value: 330uF; U/M: EA; Cap_F: 0.00047; Tolerance_%: 20; VDC_V: 35; Value2: 35V; IRMS_A: 1.82; TaMin_C: -40; TaMax_C: 105; Cap_Case: 10x20; SizeAreaWB_mm2: 144; SizeArea_mm2: 100; SizeX_mm: 10; SizeZ_mm: 21.5; AEC Category: Q200; AEC Qualified: N
signal-integrity model Cap
simulation model Cap
footprint Chemi-Con_1000x2000
pins: 1 +, 2 -

## EMK107B7104KA-T
designator C?  ValueDisplayed: 0.1µF  Value2: 16V  (hidden comment: EMK107B7104KA-T)
CAP, CERM, 0.1 µF, 16 V, +/- 10%, X7R, 0603; Manufacturer: Taiyo Yuden; Polarized: N; CompType: Capacitor; Value: 0.1uF; U/M: EA; Cap_F: 0.0000001; Tolerance_%: 10; Value1: Unknown; VDC_V: 16; TaMin_C: -55; TaMax_C: 125; Cap_Case: 0603
signal-integrity model Cap
simulation model Cap
footprint 0603
footprint 0603M
footprint 0603L
footprint 0603_HV
footprint 0603S
pins: 1, 2

## ESD_Susceptible
designator Logo?, comment ESD Susceptible  (value not drawn)  (no BOM)
ESD Susceptible Symbol; SymbolCreator: a0412235
footprint ESD_Overlay_Large
footprint ESD_Overlay_Medium
footprint ESD_Overlay_Small

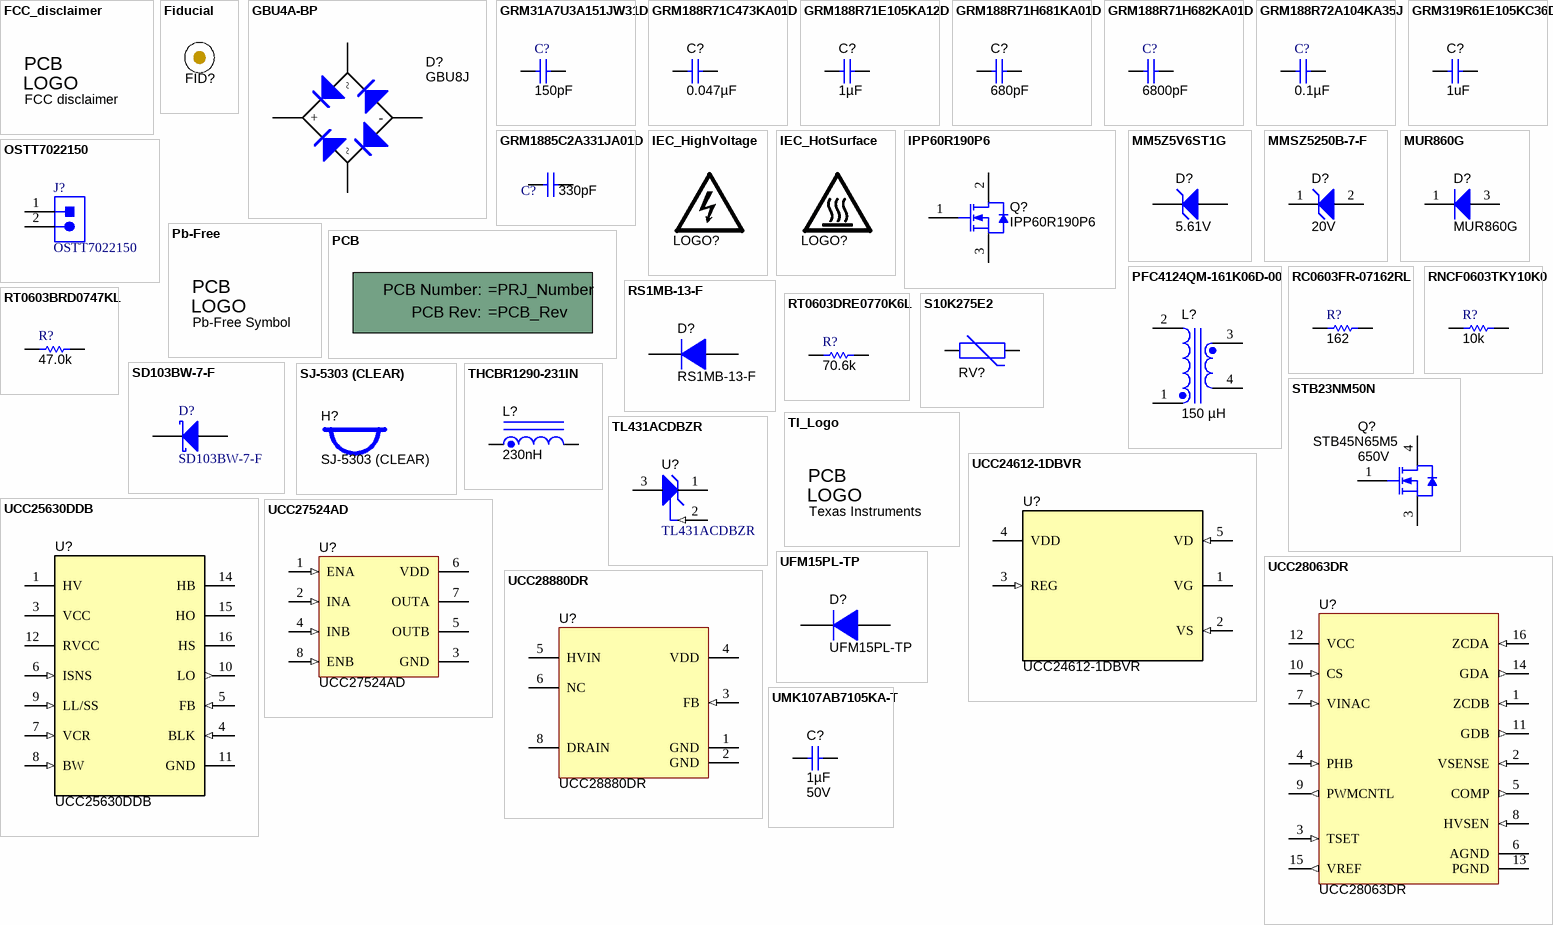
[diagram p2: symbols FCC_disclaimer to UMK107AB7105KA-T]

## FCC_disclaimer
designator Logo?, comment FCC disclaimer  (no BOM)
FCC_disclaimer; SymbolCreator: codlsc
footprint FCC_disclaimer
footprint FCC_disclaimer_stacked

## Fiducial
designator FID?  (value not drawn)
Fiducial mark.  There is nothing to buy or mount.; SymbolCreator: codlsc
footprint Fiducial10-30
footprint Fiducial10-20
footprint Fiducial15-30
footprint Fiducial20-40
footprint Fiducial6.4-20

## GBU4A-BP
designator D?, comment GBU8J
DIODE GPP 8A 600V GPP INLINE GBU; Manufacturer: Vishay; U/M: EA; Vf_V: 0.95; Io_A: 4; Value1: 4A; Vr_V: 50; Value2: 50V; TJmax_C: 150; RJC_CperW: 2.2; Type: Switching-Bridge
footprint GBU
pins: 1 +, 2 ~, 3 ~, 4 -

## GRM31A7U3A151JW31D
designator C?  ValueDisplayed: 150pF  (hidden comment: GRM31A7U3A151JW31D)
CAP, CERM, 150 pF, 1000 V, +/- 5%, U2J, 1206; Manufacturer: MuRata; Polarized: N; CompType: Capacitor; Value: 150pF; U/M: EA; Cap_F: 0.00000000015; Tolerance_%: 5; Value1: Unknown; VDC_V: 1000; Value2: 1000V; TaMin_C: -55; TaMax_C: 125; Cap_Case: 1206
signal-integrity model Cap
simulation model Cap
footprint 1206
footprint 1206M
footprint 1206L
pins: 1, 2

## GRM188R71C473KA01D
designator C?  ValueDisplayed: 0.047µF  (hidden comment: GRM188R71C473KA01D)
CAP, CERM, 0.047 µF, 16 V,+/- 10%, X7R, 0603; Manufacturer: MuRata; Polarized: N; CompType: Capacitor; Value: 0.047uF; U/M: EA; Cap_F: 0.000000047; Tolerance_%: 10; VDC_V: 16; Value2: 16V; TaMin_C: -55; TaMax_C: 125; Cap_Case: 0603; SizeArea_mm2: 1.28; SizeAreaWB_mm2: 4.68; SizeX_mm: 1.6; SizeY_mm: 0.8; SizeZ_mm: 1; AEC Category: Q200; Green_Lifecycle: Active; Green_REACh: Passed
signal-integrity model Cap
simulation model Cap
footprint 0603
footprint 0603M
footprint 0603L
footprint 0603_HV
footprint 0603S
pins: 1, 2

## GRM188R71E105KA12D
designator C?  ValueDisplayed: 1µF  (hidden comment: GRM188R71E105KA12D)
CAP, CERM, 1 µF, 25 V, +/- 10%, X7R, 0603; Manufacturer: MuRata; Polarized: N; CompType: Capacitor; Value: 1uF; U/M: EA; Cap_F: 0.000001; Tolerance_%: 10; Value1: Unknown; VDC_V: 25; Value2: 25V; TaMin_C: -55; TaMax_C: 125; Cap_Case: 0603
signal-integrity model Cap
simulation model Cap
footprint 0603
footprint 0603M
footprint 0603L
footprint 0603_HV
footprint 0603S
pins: 1, 2

## GRM188R71H681KA01D
designator C?  ValueDisplayed: 680pF  (hidden comment: GRM188R71H681KA01D)
CAP, CERM, 680 pF, 50 V, +/- 10%, X7R, 0603; Manufacturer: MuRata; Polarized: N; CompType: Capacitor; Value: 680pF; U/M: EA; Cap_F: 0.00000000068; Tolerance_%: 10; Value1: Unknown; VDC_V: 50; Value2: 50V; TaMin_C: -55; TaMax_C: 125; Cap_Case: 0603
signal-integrity model Cap
simulation model Cap
footprint 0603
footprint 0603M
footprint 0603L
footprint 0603_HV
footprint 0603S
pins: 1, 2

## GRM188R71H682KA01D
designator C?  ValueDisplayed: 6800pF  (hidden comment: GRM188R71H682KA01D)
CAP, CERM, 6800 pF, 50 V, +/- 10%, X7R, 0603; Manufacturer: MuRata; Polarized: N; CompType: Capacitor; Value: 6800pF; U/M: EA; Cap_F: 0.0000000068; Tolerance_%: 10; Value1: Unknown; VDC_V: 50; Value2: 50V; TaMin_C: -55; TaMax_C: 125; Cap_Case: 0603
signal-integrity model Cap
simulation model Cap
footprint 0603
footprint 0603M
footprint 0603L
footprint 0603_HV
footprint 0603S
pins: 1, 2

## GRM188R72A104KA35J
designator C?  ValueDisplayed: 0.1µF  (hidden comment: GRM188R72A104KA35J)
CAP, CERM, 0.1 µF, 100 V, +/- 10%, X7R, 0603; Manufacturer: MuRata; Polarized: N; CompType: Capacitor; Value: 0.1uF; U/M: EA; Cap_F: 0.0000001; Tolerance_%: 10; Value1: Unknown; VDC_V: 100; Value2: 100V; TaMin_C: -55; TaMax_C: 125; Cap_Case: 0603
signal-integrity model Cap
simulation model Cap
footprint 0603
footprint 0603M
footprint 0603L
footprint 0603_HV
footprint 0603S
pins: 1, 2

## GRM319R61E105KC36D
designator C?  ValueDisplayed: 1uF  (hidden comment: GRM319R61E105KC36D)
CAP, CERM, 1uF, 25V, +/-10%, X5R, 1206; Manufacturer: MuRata; Polarized: N; CompType: Capacitor; U/M: EA; Cap_F: 0.000001; Tolerance_%: 10; ESR_Ohm: 0.01; Value1: 0.01 ohm; VDC_V: 25; TaMin_C: -55; TaMax_C: 85; Cap_Case: 1206
signal-integrity model Cap
simulation model Cap
footprint 1206
footprint 1206M
footprint 1206L
pins: 1, 2

## GRM1885C2A331JA01D
designator C?  ValueDisplayed: 330pF  (hidden comment: GRM1885C2A331JA01D)
CAP, CERM, 330 pF, 100 V, +/- 5%, C0G/NP0, 0603; Manufacturer: MuRata; Polarized: N; CompType: Capacitor; Value: 330pF; U/M: EA; Cap_F: 0.00000000033; Tolerance_%: 5; Value1: Unknown; VDC_V: 100; Value2: 100V; TaMin_C: -55; TaMax_C: 125; Cap_Case: 0603
signal-integrity model Cap
simulation model Cap
footprint 0603
footprint 0603M
footprint 0603L
footprint 0603_HV
footprint 0603S
pins: 1, 2

## IEC_HighVoltage
designator LOGO?, comment DANGER HIGH VOLTAGE  (value not drawn)  (no BOM)
IEC 61010-1 High Voltage Warning; SymbolCreator: a0412235
footprint IEC_HighVoltage_Large
footprint IEC_HighVoltage_Medium
footprint IEC_HighVoltage_Small

## IEC_HotSurface
designator LOGO?, comment CAUTION HOT SURFACE  (value not drawn)  (no BOM)
IEC 61010-1 Hot Surface Warning; SymbolCreator: a0412235
footprint IEC_HotSurface_Large
footprint IEC_HotSurface_Medium
footprint IEC_HotSurface_Small

## IPP60R190P6
designator Q?
MOSFET, N-CH, 650 V, 20.2 A, TO-220AB; Manufacturer: Infineon Technologies; Alternate Manufacturer: None; U/M: EA; ChType: N; Value: 650V; VdsMax_V: 650; Value1: ? ohm; Value2: 37 nC; QgTyp_nC: 37; Vgs_V: 20; IdsMax_A: 20.2; SizeAreaWB_mm2: 79.3; SizeArea_mm2: 45.9; SizeX_mm: 10.2; SizeY_mm: 4.5; SizeZ_mm: 19.4; AEC Category: Q101
footprint TO-220AB
footprint TO-220AB_HORIZONTAL
footprint TO-220AB_HORIZONTAL_SMT
footprint TO-220AB_100mil
footprint TO-220AB_Horizontal_100mil
footprint TO-220AB_Horizontal_100mil_Standoff2300
pins: 1 G, 2 D, 3 S
1 alternate drawing of the same symbol

## MM5Z5V6ST1G
designator D?, comment 5.61V
Diode, Zener, 5.61 V, 500 mW, SOD-523; PartNumber: MM5Z5V6ST1G; Manufacturer: ON Semiconductor; SymbolCreator: a0412235; U/M: EA; Power_W: 0.5; Vz_V: 5.61; Value1: 0.5W; RJA_CperW: 250
signal-integrity model Diode
footprint SOD-523
pins: 1 K, 2 A

## MMSZ5250B-7-F
designator D?  value 20V  (hidden comment: MMSZ5250B-7-F)
Diode, Zener, 20V, 500mW, SOD-123; Manufacturer: Diodes Inc.; U/M: EA; Power_W: 0.5; Vz_V: 20; Value1: 0.5W; RJA_CperW: 350
signal-integrity model Diode
footprint SOD-123
pins: 1 K, 2 A

## MUR860G
designator D?
Diode, Ultrafast, 600V, 8A, TH; Manufacturer: ON Semiconductor; SymbolCreator: a0412235; Value: 0.98V; U/M: EA; Vf_V: 0.98; Io_A: 8; Vr_V: 600; TJmax_C: 175; RJC_CperW: 4.75
signal-integrity model Diode SI (Model Description)
footprint TO-220AC
footprint TO-220AC_HORIZ
pins: 1 K, 3 A

## OSTT7022150
designator J?
Terminal Block, 30A, 9.52mm (.375) Pitch, 2-Pos, TH; Manufacturer: On-Shore Technology; SymbolCreator: a0412235; CompType: Connector; U/M: EA
footprint TERM_BLK_OSTT7022150
pins: 1, 2
1 alternate drawing of the same symbol

## Pb-Free
designator Logo?, comment Pb-Free Symbol  (no BOM)
SymbolCreator: a0412235
footprint Pb-Free_Overlay_Medium
footprint Pb-Free_Overlay_Small

## PCB
designator !PCB?, comment Printed Circuit Board  (value not drawn)  (mechanical)
Manufacturer: Any; SymbolCreator: a0412235; CompType: PCB
1 alternate drawing of the same symbol

## PFC4124QM-161K06D-00
designator L?, comment value 150 µH  (hidden comment: PFC4124QM-151XXX)
Transformer, 160 uH, TH; Manufacturer: TDK; SymbolCreator: Altium; U/M: EA
footprint TDK_PFC4124QM-161K06D-00
footprint WE-CMBH_Updated (THT Inductor, 4-Leads, Body 28 x 32.5mm)
pins: 1, 2, 3, 4

## RC0603FR-07162RL
designator R?  ValueDisplayed: 162  (hidden comment: RC0603FR-07162RL)
RES, 162, 1%, 0.1 W, 0603; Manufacturer: Yageo America; CompType: Resistor; Value: 162; Value_Code: 162R; Tolerance_%: 1; Power_W: 0.1; Value2: 0.1W; VDC_V: 150; TempCo: 200 ppm/C; EIA_Code: E96; U/M: EA
signal-integrity model Resistor
simulation model Resistor
footprint 0603
footprint 0603M
footprint 0603L
footprint 0603_HV
footprint 0603S
pins: 1, 2

## RNCF0603TKY10K0
designator R?  ValueDisplayed: 10k  (hidden comment: RNCF0603TKY10K0)
RES, 10 k, 0.01%, 0.063 W, 0603; Manufacturer: Stackpole Electronics Inc; CompType: Resistor; Value: 10k; Res_ohm: 10000; Value_Code: 10k0; Tolerance_%: 0.01; Power_W: 0.063; Value2: 0.063W; VDC_V: 50; TempCo: 5 ppm/C; U/M: EA
signal-integrity model Resistor
simulation model Resistor
footprint 0603
footprint 0603M
footprint 0603L
footprint 0603_HV
footprint 0603S
pins: 1, 2

## RS1MB-13-F
designator D?
Diode, P-N, 1000 V, 1 A, SMB; Manufacturer: Diodes Inc.; U/M: EA; Vf_V: 1.3; Value: 1000V; Value1: 1A; Value2: 1.3V; Io_A: 1; Vr_V: 1000; TJmax_C: 150; RJC_CperW: 20; SizeAreaWB_mm2: 44.156; SizeArea_mm2: 21.336; SizeX_mm: 5.6; SizeY_mm: 3.81; SizeZ_mm: 2.6; AEC Category: Q101; Green_Lifecycle: Active; Green_REACh: Passed
signal-integrity model Diode
footprint SMB
pins: 1 K, 2 A

## RT0603BRD0747KL
designator R?  ValueDisplayed: 47.0k  (hidden comment: RT0603BRD0747KL)
RES, 47.0 k, 0.1%, 0.1 W, 0603; Manufacturer: Yageo America; CompType: Resistor; Value: 47.0k; Res_ohm: 47000; Value_Code: 47k0; Tolerance_%: 0.1; Value2: 0.1W; VDC_V: 75; TempCo: 25 ppm/C; EIA_Code: E192; U/M: EA
signal-integrity model Resistor
simulation model Resistor
footprint 0603
footprint 0603M
footprint 0603L
footprint 0603_HV
footprint 0603S
pins: 1, 2

## RT0603DRE0770K6L
designator R?  ValueDisplayed: 70.6k  (hidden comment: RT0603DRE0770K6L)
RES, 70.6 k, 0.5%, 0.1 W, 0603; Manufacturer: Yageo America; CompType: Resistor; Value: 70.6k; Res_ohm: 70600; Value_Code: 70k6; Tolerance_%: 0.5; Power_W: 0.1; Value2: 0.1W; VDC_V: 75; TempCo: 50 ppm/C; EIA_Code: E192; U/M: EA
signal-integrity model Resistor
simulation model Resistor
footprint 0603
footprint 0603M
footprint 0603L
footprint 0603_HV
footprint 0603S
pins: 1, 2

## S10K275E2
designator RV?  (value not drawn)
Varistor 275V RMS 10MM Radial, TH; Manufacturer: EPCOS Inc; SymbolCreator: a0412235
footprint VAR_S10K275E2
pins: 1, 2

## SD103BW-7-F
designator D?
Diode, Schottky, 30 V, 0.35 A, SOD-123; Manufacturer: Diodes Inc.; U/M: EA; Vf_V: 0.55; Value: 30V; Value1: 0.35A; Value2: 0.55V; Io_A: 0.35; Vr_V: 30
signal-integrity model Diode
simulation model DI_SD103BW
footprint SOD-123
pins: 1 K, 2 A

## SJ-5303 (CLEAR)
designator H?
Bumpon, Hemisphere, 0.44 X 0.20, Clear; Manufacturer: 3M; SymbolCreator: a0412235
footprint Bumpon_SJ5003Transparent (3M Hemispherical Bumpon transparent)

## STB23NM50N
designator Q?, comment STB45N65M5  value 650V
MOSFET N CH 650V 35A D2PAK; Manufacturer: ST Microelectronics; Alternate Manufacturer: None; U/M: EA; VdsMax_V: 650; Value1: ? ohm; Value2: 45 nC; QgTyp_nC: 45; Vgs_V: 25; IdsMax_A: 17
footprint DDPAK
pins: 1 G, 3 S, 4 D

## THCBR1290-231IN
designator L?  ValueDisplayed: 230nH  (hidden comment: THCBR1290-231IN)
Inductor, Ferrite, 230 nH, 56 A, 0.0005 ohm, TH; Manufacturer: Delta Electronics Inc.; Value: 230nH; SymbolCreator: a0412235; Ind_H: 230.0E-9; Imax_A: 56; Irms: 0A @ 0C rise; Isat: 56A @ 0% inductance drop; DCR_ohm: 0.0005; Value2: 56A; SizeAreaWB_mm2: 151.8; SizeArea_mm2: 106.2; SizeX_mm: 11.8; SizeY_mm: 9; SizeZ_mm: 9.2; AEC Category: Q200; Green_Lifecycle: Not Set; Green_REACh: Incomplete
signal-integrity model Inductor
simulation model Inductor
footprint THCBR1290
pins: 1, 2

## TI_Logo
designator Logo?, comment Texas Instruments  (no BOM)
Texas Instrument Corporate Signature; SymbolCreator: codlsc
footprint TI_Stacked_SolderMask_Medium
footprint TI_Stacked_SolderMask_Small
footprint TI_Stacked_Overlay_Medium
footprint TI_Stacked_Overlay_Small
footprint TI_Horizontal_SolderMask_Medium
footprint TI_Horizontal_SolderMask_Small
footprint TI_Horizontal_Overlay_Medium
footprint TI_Horizontal_Overlay_Small
footprint TI_Symbol_SolderMask_Small
footprint TI_Symbol_Overlay_Medium
footprint TI_Symbol_Overlay_Small
footprint TI_Symbol_SolderMask_Medium

## TL431ACDBZR
designator U?
Adjustable Precision Shunt Regulator, 34 ppm / degC, 100 mA, 0 to 70 degC, 3-pin SOT-23 (DBZ), Green (RoHS & no Sb/Br); Manufacturer: Texas Instruments; Alternate PartNumber: Equivalent; Initial Accuracy @ 25/deg C(%): 1; Iout/Iz(Max)(mA): 100; Min Iz for Regulation(uA): 600; Rating: Catalog; SubFamily: Shunt Voltage Reference; Temp Coeff(Typ)(ppm/ degree C): 34; VO Adj(Max)(V): 36; VO Adj(Min)(V): 2.495
footprint DBZ0003A_N (SOT23, 3-Leads, Body 2.92x1.3 mm, Pitch 0.95 mm, IPC Medium Density)
footprint DBZ0003A_L (SOT23, 3-Leads, Body 2.92x1.3 mm, Pitch 0.95 mm, IPC High Density)
footprint DBZ0003A_M (SOT23, 3-Leads, Body 2.92x1.3 mm, Pitch 0.95 mm, IPC Low Density)
pins: 1 CATHODE, 2 REF (in), 3 ANODE

## UCC24612-1DBVR
designator U?
UCC24612-1DBV, DBV0005A (SOT-23-5); Alternate PartNumber: UCC24612-1DBVT; Manufacturer: Texas Instruments; SymbolCreator: Altium; SizeArea_mm2: 8.12; SizeAreaWB_mm2: 14.82; SizeX_mm: 2.8; SizeY_mm: 2.9; SizeZ_mm: 1.45; CompType: IC; U/M: EA
footprint DBV0005A_N
footprint DBV0005A_M
footprint DBV0005A_L
pins: 1 VG (power), 2 VS (in), 3 REG (in), 4 VDD (power), 5 VD (in)
1 alternate drawing of the same symbol

## UCC25630DDB
designator U?
Enhanced LLC Resonant Controller with Driver, DDB0014A (SOIC-14); Manufacturer: Texas Instruments; SymbolCreator: Altium; SizeArea_mm2: 59.4; SizeAreaWB_mm2: 95.2; SizeX_mm: 6; SizeY_mm: 9.9; SizeZ_mm: 1.75; CompType: IC; U/M: EA
footprint DDB0014A
pins: 1 HV (power), 3 VCC (power), 4 BLK (in), 5 FB (in), 6 ISNS (in), 7 VCR (in), 8 BW (in), 9 LL/SS (in), 10 LO (out), 11 GND (power), 12 RVCC (power), 14 HB (power), 15 HO (power), 16 HS (power)

## UCC27524AD
designator U?
Dual 5-A High-Speed Low-Side Gate Driver, D0008A; Manufacturer: Texas Instruments; SymbolCreator: a0411947; CompType: IC; U/M: EA
footprint D0008A_N
footprint D0008A_M
footprint D0008A_L
pins: 1 ENA (in), 2 INA (in), 3 GND (power), 4 INB (in), 5 OUTB (power), 6 VDD (power), 7 OUTA (power), 8 ENB (in)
